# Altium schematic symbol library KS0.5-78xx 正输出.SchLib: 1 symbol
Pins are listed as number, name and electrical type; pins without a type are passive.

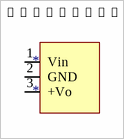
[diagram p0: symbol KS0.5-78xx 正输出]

## KS0.5-78xx 正输出
designator *
footprint Model Name (Footprint not found)
pins: 1 Vin, 2 GND, 3 +Vo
